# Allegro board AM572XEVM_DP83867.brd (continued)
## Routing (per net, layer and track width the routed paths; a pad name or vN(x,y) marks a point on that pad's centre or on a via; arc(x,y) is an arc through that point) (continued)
GND_EARTH: length 325.7
  TOP w0.381: 109.66,106.27 P5.SHLD1 107.78,106.27 ; 91,106.27 P5.SHLD2 92.88,106.27
  TOP w0.762: P7.S2 P7.S4 ; S2.4 60.45,4.02 v1(60.45,0.89) ; S2.3 51.94,3.97 v1(51.94,0.89) ; v1(25.27,106.68) 25.27,103.26 S1.4 S1.3 33.15,103.26 33.15,106.68
  GND_L2 w0.381: 91,106.27 P5.SHLD2 92.88,106.27 ; 107.78,106.27 P5.SHLD1 109.66,106.27
  INT_L3 w0.381: 107.78,106.27 P5.SHLD1 109.66,106.27 ; 91,106.27 P5.SHLD2 92.88,106.27
  GND_L4 w0.381: 92.88,106.27 P5.SHLD2 91,106.27 ; 109.66,106.27 P5.SHLD1 107.78,106.27
  SIG_L5 w0.381: 109.66,106.27 P5.SHLD1 107.78,106.27 ; 92.88,106.27 P5.SHLD2 91,106.27
  PWR_L6 w0.381: 92.88,106.27 P5.SHLD2 91,106.27 ; 107.78,106.27 P5.SHLD1 109.66,106.27
  PWR_L7 w0.381: 92.88,106.27 P5.SHLD2 91,106.27 ; 107.78,106.27 P5.SHLD1 109.66,106.27
  SIG_L8 w0.381: 107.78,106.27 P5.SHLD1 109.66,106.27 ; 92.88,106.27 P5.SHLD2 91,106.27
  SIG_L8 w0.762: P15.21 P15.19
  GND_L9 w0.381: 107.78,106.27 P5.SHLD1 109.66,106.27 ; 92.88,106.27 P5.SHLD2 91,106.27
  SIG_L10 w0.381: 92.88,106.27 P5.SHLD2 91,106.27 ; 107.78,106.27 P5.SHLD1 109.66,106.27
  SIG_L10 w0.762: P13.10 P13.11 P15.19 110.08,11.42
  GND_L11 w0.381: 107.78,106.27 P5.SHLD1 109.66,106.27 ; 91,106.27 P5.SHLD2 92.88,106.27
  BOTTOM w0.381: D10.1 v1(47.12,0.89) ; C231.2 83.55,1.81 P7.S3 ; R402.2 18.92,96.27 ; R402.2 19.46,95.84 ; R402.2 19.46,96.69 ; v1(113.03,106.68) 112.93,106.58 113.03,106.48 113.03,105.53 C215.2 ; C472.2 16.41,4.32 MH1.1 16.61,3.3 R400.2 ; C472.2 19.71,3.89 ; C472.2 19.71,4.75 ; C472.2 R400.2 ; C474.2 18.92,97.28 ; C474.2 19.46,96.85 ; C474.2 19.46,97.71 ; 92.88,106.27 P5.SHLD2 91,106.27 ; R331.2 100.38,106.63 v1(100.33,106.68) ; 121.24,90.39 R403.2 ; R403.2 121.67,93.8 MH4.1 120.65,93.8 C475.2 ; R403.2 122.09,90.39 ; 120.22,90.39 C475.2 ; C475.2 121.08,90.39 ; R299.2 v1(84.58,106.68) ; R385.2 v1(60.45,0.89) ; 117.06,2.87 R401.2 ; R401.2 C473.2 ; R401.2 117.45,3.73 ; R401.2 120.55,3.3 MH2.1 120.75,4.32 C473.2 ; 19.71,2.87 R400.2 ; R400.2 20.1,2.87 ; C473.2 117.45,3.89 ; C473.2 117.45,4.75 ; D8.1 v1(34.32,0.89) ; C216.2 33.15,106.68 ; 110.08,17.11 110.11,17.14 R300.2 ; 107.78,106.27 P5.SHLD1 109.66,106.27 ; D9.1 v1(29.24,0.89) ; R387.2 v1(63.75,106.68) ; C230.2 v1(51.94,0.89) ; C441.2 v1(51.82,106.68) ; v1(25.78,106.68) 25.27,106.68 v1(25.27,106.68) R332.2 ; 24,106.68 24,106.14 R384.1 24.51,106.14 24.51,106.68 ; R386.2 89.17,1.81 P7.S1 ; C419.1 79.76,11.46 P13.10 ; D11.1 v1(42.04,0.89) ; C415.2 v1(70.36,106.68)
  BOTTOM w0.762: P5.SHLD4 91.96,89 91.96,96.33 91.08,97.21 91.08,102.54 91.94,103.39 P5.SHLD2 ; P11.MTG2 49.94,100.68 P11.MTG4 49.94,106.32 50.29,106.68 v1(51.82,106.68) v1(54.61,106.68) v1(57.15,106.68) v1(59.69,106.68) v1(62.23,106.68) v1(63.75,106.68) 65.28,106.68 65.63,106.32 P11.MTG3 65.63,100.68 P11.MTG1 ; v1(79.76,0.89) 79.76,11.39 P13.10 ; S2.4 S2.3 ; P5.SHLD1 108.72,104.41 109.96,103.17 109.96,99.44 108.72,98.21 P5.SHLD3 ; v1(110.11,0.89) 110.11,11.39 110.08,11.42 110.08,17.11 ; P6.16 P6.17 68.27,106.12 68.83,106.68 v1(70.36,106.68) v1(72.39,106.68) v1(74.93,106.68) v1(77.47,106.68) v1(80.01,106.68) v1(82.55,106.68) v1(84.58,106.68) 85.98,106.68 86.67,105.99 P6.14 P6.15
  vias: v1(13.46,104.01) v1(13.46,101.47) v1(13.46,98.93) v1(13.46,91.31) v1(13.46,88.77) v1(13.46,86.23) v1(13.46,83.69) v1(13.46,81.15) v1(13.46,78.61) v1(13.46,76.07) v1(13.46,73.53) v1(13.46,70.99) v1(13.46,68.45) v1(13.46,65.91) v1(13.46,63.37) v1(13.46,60.83) v1(13.46,58.29) v1(13.46,55.75) v1(13.46,53.21) v1(13.46,50.67) v1(13.46,48.13) v1(13.46,45.59) v1(13.46,43.05) v1(13.46,40.51) v1(13.46,37.97) v1(13.46,35.43) v1(13.46,32.89) v1(13.46,30.35) v1(13.46,27.81) v1(13.46,25.27) v1(13.46,22.73) v1(13.46,20.19) v1(13.46,17.65) v1(13.46,15.11) v1(13.46,12.57) v1(13.46,10.03) v1(13.46,7.49) v1(14.73,105.84) v1(16.51,106.68) v1(19.05,106.68) v1(19.05,0.89) v1(21.59,106.68) v1(21.59,0.89) v1(24.13,106.68) v1(24.13,0.89) v1(26.54,106.68) v1(29.21,106.68) v1(31.75,106.68) v1(31.75,0.89) v1(34.42,106.68) v1(36.83,106.68) v1(39.37,106.68) v1(41.91,106.68) v1(44.45,106.68) v1(44.45,0.89) v1(46.99,106.68) v1(49.53,106.68) v1(54.61,0.89) v1(57.15,0.89) v1(61.59,0.89) v1(63.63,0.89) v1(64.77,0.89) v1(67.31,106.68) v1(67.31,0.89) v1(69.85,0.89) v1(72.39,0.89) v1(75.95,0.89) v1(78.11,0.89) v1(82.55,0.89) v1(87.63,106.68) v1(90.17,106.68) v1(90.17,0.89) v1(92.71,106.68) v1(92.71,0.89) v1(95.25,106.68) v1(95.25,0.89) v1(97.79,106.68) v1(97.79,0.89) v1(100.33,0.89) v1(102.87,106.68) v1(102.87,0.89) v1(105.41,106.68) v1(105.41,0.89) v1(107.95,106.68) v1(107.95,0.89) v1(110.49,106.68) v1(113.03,0.89) v1(115.57,106.68) v1(115.57,0.89) v1(118.11,106.68) v1(118.11,0.89) v1(120.65,106.68) v1(122.66,105.89) v1(123.7,104.01) v1(123.7,101.47) v1(123.7,98.93) v1(123.7,88.52) v1(123.7,85.83) v1(123.7,83.69) v1(123.7,81.15) v1(123.7,78.61) v1(123.7,76.07) v1(123.7,73.53) v1(123.7,70.99) v1(123.7,68.45) v1(123.7,65.91) v1(123.7,63.37) v1(123.7,60.83) v1(123.7,58.29) v1(123.7,55.75) v1(123.7,53.21) v1(123.7,50.67) v1(123.7,48.13) v1(123.7,45.59) v1(123.7,43.05) v1(123.7,40.51) v1(123.7,37.97) v1(123.7,35.43) v1(123.7,32.89) v1(123.7,30.35) v1(123.7,27.81) v1(123.7,25.27) v1(123.7,22.73) v1(123.7,20.19) v1(123.7,17.65) v1(123.7,15.11) v1(123.7,12.57) v1(123.7,10.03) v1(123.7,7.49)
GND_SIGNAL: length 24
  TOP w0.254: v1(55.12,19.81) 55.12,19.78 55.37,19.53 U18.17 56.67,19.53 v1(57.15,19.05) ; v1(57.17,14.5) U18.26 57.17,16.49 v1(57.15,16.51)
  TOP w0.381: C247.2 53.5,23.02 53.98,23.5 v1(55.12,23.5)
  SIG_L8 w0.381: 43.26,4.64 P9.1 ; P9.1 44.58,5.58 ; P9.1 44.58,3.7 ; P9.1 45.9,4.64 ; P8.1 33.1,4.64 ; P8.1 31.78,5.58 ; P8.1 31.78,3.7 ; P8.1 30.45,4.64
  BOTTOM w0.381: R235.2 v1(47.75,13.72) ; FB9.2 56.52,22.35 55.88,21.72 v1(55.88,21.08) ; R234.2 v1(41.15,13.72) ; C248.2 57.75,14.72 57.53,14.5 v1(57.17,14.5) ; v1(52.2,16) 52.58,16.38 C249.2 ; R226.2 v1(35.43,14.35) ; R228.2 v1(28.07,14.35)
  vias: v1(57.15,17.78) v1(58.42,19.05) v1(58.42,17.78) v1(58.42,16.51) v1(59.69,19.05) v1(59.69,17.78) v1(59.69,16.51)
VBUS_DET: length 51.9
  TOP w0.12: v1(68.96,26.92) 68.96,28.7 69.47,29.21 69.98,29.21 70.59,29.82 70.59,30.41 U11.B11
  SIG_L10 w0.094: v1(68.96,26.92) 68.96,26.29 71.63,23.62 74.68,23.62 77.22,21.08 77.22,10.67 78.87,9.02 98.17,9.02 v1(98.81,9.65)
  BOTTOM w0.12: R414.2 97.7,8.03 97.79,8.13 97.79,8.89 97.88,8.98 R413.2 98.3,9.4 98.55,9.65 v1(98.81,9.65)
VCC_SENSE: length 2.8
  TOP w0.12: U5.B3 v2(70.99,76.01)
  BOTTOM w0.12: v2(70.99,76.01) 71.38,75.62 71.95,75.62 72.55,76.22 72.55,76.23 72.7,76.38 R30.2
VCC_SENSE2: length 2
  TOP w0.12: R29.2 73.38,69.21 U5.A11
VDD_1.1: length 19.4
  TOP w0.254: v1(97.92,33.02) 97.84,33.09 U17.31 ; U17.8 92.46,25.39 92.46,24.77 v1(92.33,24.64) ; 88.27,32.59 87.57,32.59 v1(87.53,32.64) ; v1(97.92,31.62) 97.89,31.6 U17.28 ; U17.5 90.96,24.67 v1(90.93,24.64) ; v1(87.5,29.59) 87.51,29.6 88.27,29.6 ; v1(97.92,28.07) 97.89,28.09 U17.21 ; v1(94.87,26.42) 94.96,26.32 U17.13
  BOTTOM w0.254: C486.1 94.93,26.47 v1(94.87,26.42) ; C483.1 v1(87.5,29.59) ; v1(97.92,33.02) 97.66,32.77 C489.1 ; v1(90.93,24.64) C484.1 ; C488.1 v1(97.92,31.62) ; C487.1 v1(97.92,28.07) ; v1(92.33,24.64) 92.46,24.77 C485.1 ; C482.1 v1(87.53,32.64)
  BOTTOM w0.305: R201.1 105.54,37.08 105.02,37.6 U16.9 U16.10 103.71,36.53 v1(103.63,36.45)
  BOTTOM w0.381: v1(97.92,28.07) 97.92,28.7 97.66,28.96 C481.1 ; v1(103,36.45) v1(103.63,36.45)
VDD_1V0: length 20.4
  TOP w0.381: R471.1 87.63,75.16 v1(87.63,75.49) v1(87.05,75.49) ; 111.66,75.34 v1(112.06,75.74) ; 111.66,75.34 v1(111.23,75.77) ; 111.66,75.34 R473.1 ; U5.J8 v2(64.59,71.21)
  SIG_L8 w0.381: 85.86,78.04 TP28.1 ; TP28.1 86.76,78.04 ; TP28.1 86.76,78.93 ; TP28.1 85.86,78.93
  SIG_L10 w0.254: v2(64.59,71.21) 64.58,71.21 63.98,71.81 60.6,71.81 60.07,71.27 60.07,69.32 56.77,66.01 v1(54.41,66.01)
  vias: v1(54.41,66.62) v1(54.41,65.43)
VDD_1V8: length 57.5
  TOP w0.254: U11.P8 v2(72.99,40.01) U11.N8 v2(72.99,39.21) U11.M8 ; U11.W17 v2(64.99,44.81) U11.W18 v2(64.19,44.81) ; U11.H17 v2(64.99,35.21) U11.G18 v2(64.19,34.41) ; U11.M8 v2(72.19,38.41) U11.M9 ; U11.M8 v2(72.99,38.41) ; U11.V21 v2(61.79,44.01) ; v2(61.79,44.01) U11.V22 v2(60.99,44.01) ; v2(61.79,44.01) U11.W21 v2(61.79,44.81) U11.Y21 v2(61.79,45.61) ; U11.N21 v2(62.59,40.01) ; U11.N21 v2(61.79,39.21) ; U11.N21 v2(61.79,40.01) U11.P21 v2(62.59,40.01) ; v2(62.59,40.01) U11.P20 ; U11.J21 v2(61.79,36.01) U11.J22 v2(60.99,36.01) ; U11.R8 v2(72.99,41.61) U11.T8 v2(72.99,42.41) ; U11.Y7 v2(73.79,45.61) U11.AA7 v2(73.79,46.41) ; v2(63.39,46.41) U11.AA19 v2(64.19,46.41) U11.AA18 ; v2(62.99,68.81) U5.L11
  TOP w0.381: v1(56.01,54.74) 56.01,55.12 56.64,55.75 56.64,59.56 L9.2 ; v1(78.99,73.66) 80.39,73.66 81.37,72.68 R302.2
  BOTTOM w0.254: v2(64.19,46.41) 64.5,46.72 C185.1 ; C195.1 72.67,38.72 v2(72.99,38.41) ; C188.1 73.47,45.29 v2(73.79,45.61) ; v2(72.99,42.41) 72.67,42.09 C194.1 ; v2(73.79,46.41) 73.47,46.09 C187.1 ; C186.1 65.3,34.89 v2(64.99,35.21) ; C192.1 64.5,44.49 v2(64.19,44.81) ; C191.1 U11.Y21 v2(61.79,44.81) ; C193.1 U11.V21 v2(61.79,44.01) ; C196.1 61.3,36.32 v2(60.99,36.01)
  BOTTOM w0.381: Q9.3 78.87,74.26 78.87,73.79 v1(78.99,73.66) 80.65,73.66 81.06,74.07 81.06,74.55 ; 81.06,74.55 R425.2 ; 81.06,74.55 81.1,74.51 U43.3 ; v1(56.01,54.74) 56.01,54.99 56.39,55.37 57.95,55.37 C190.1 ; C189.1 v1(58.67,59.94) ; R420.2 50,73.03 U35.3 Q8.3 55.08,73.19 55.88,72.39 55.88,70.61 v1(55.12,69.85)
  vias: v1(58.67,60.58) v1(58.67,59.31)
VDD_2V5: length 15.5
  TOP w0.254: v2(70.99,77.62) 70.59,77.22 U5.B1
  TOP w0.381: R472.1 84.86,74.63 ; 84.86,74.63 v1(84.38,75.11) ; 84.86,74.63 84.79,74.63 v1(84.43,74.27) ; R475.1 109.58,75.34 ; 109.58,75.34 v1(109.14,75.77) ; 109.58,75.34 v1(110.01,75.77)
  PWR_L6 w0.381: TP29.1 86.73,76.77 ; TP29.1 85.84,76.77 ; TP29.1 86.73,75.88 ; TP29.1 85.84,75.88
  SIG_L10 w0.254: v1(71.4,85.45) 71.4,83.21 72.59,82.02 72.59,81 71.98,80.39 71.98,78.61 v2(70.99,77.62)
  vias: v1(70.66,85.46) v1(72.14,85.45)
VDD_3V3: length 220.3
  TOP w0.203: v2(93.82,45.57) U22.M4 ; 93.34,47.62 93.34,47.09 U22.P5 U22.N4 ; v2(92.58,42.06) U22.C6
  TOP w0.254: U11.B23 v2(60.19,30.41) ; U11.AD7 v2(73.79,48.81) U11.AE7 ; U11.H11 v2(70.59,35.21) U11.H10 v2(71.39,35.21) U11.H9 v2(72.19,35.21) U11.H8 ; U6.8 85.84,82.28 86.11,82.02 C30.1 ; v1(96.14,33.53) 95.96,33.71 U17.34 ; v2(65.79,35.21) U11.H16 v2(66.59,35.21) ; U11.R10 v2(71.39,41.61) ; v2(76.19,44.81) U11.W4 v2(75.39,44.81) U11.W5 ; U11.E22 v2(60.99,32.81) U11.D22 v2(60.99,32.01) ; U11.H8 v2(72.99,35.21) ; U11.H8 v2(72.99,36.01) U11.J8 v2(72.99,36.81) U11.K8 ; U17.16 96.46,26.1 v1(96.14,26.42) ; v2(66.59,35.21) U11.G15 v2(66.59,34.41) ; v2(66.59,35.21) U11.H15 ; U11.B6 v2(74.59,30.41) ; v1(89.53,26.42) 89.35,26.6 88.27,26.6 ; U4.5 68.33,18.41 67.85,18.89 R213.1 ; v2(76.19,39.21) U11.N4 v2(75.39,39.21) U11.N5 ; v2(63.39,35.21) U11.H19 v2(64.19,35.21) U11.H18 ; U33.16 v1(76.84,86.36) ; U11.E16 v2(65.79,32.81) U11.D16 v2(65.79,32.01) ; v2(76.19,34.41) U11.G4 v2(75.39,34.41) U11.G5 ; U11.C24 v2(59.39,31.21) ; R15.1 71.41,17.94 71.75,18.29 71.75,18.54 72.1,18.89 R212.1 ; v2(69.39,70.41) U5.D9 ; v2(76.19,42.41) U11.T4 v2(75.39,42.41) U11.T5 ; U11.P10 v2(71.39,40.01) ; U20.8 30.34,37.58 30.23,37.47 30.23,37.08 v1(30.23,37.08) U20.7 ; U33.10 v1(80.64,86.35) ; v2(71.39,32.01) U11.D10 v2(71.39,32.81) U11.E10 ; 88.27,32.1 89.19,32.1 v1(89.28,32) ; v1(66.04,94.74) 65.48,95.3 U21.23 ; U27.10 26.43,19.95 26.25,19.77 25.1,19.77 24.93,19.95 R286.1 ; U11.E5 v2(75.39,32.81) ; U11.E3 v2(76.99,32.81) ; U33.20 v1(76.84,83.31) ; U11.R7 v2(73.79,41.61) ; R474.1 111.02,59.05 v1(110.72,58.75) ; U33.6 v1(80.64,83.31) ; U11.U10 v2(71.39,43.21) ; v2(74.59,47.21) U11.AB6 v2(73.79,47.21) U11.AB7 ; U11.AD5 v2(75.39,48.81) ; U11.AF5 v2(75.39,49.61)
  TOP w0.381: R212.1 72.26,20.32 v1(71.75,20.83) ; v1(66.68,20.83) 67.44,20.07 R213.1 C15.1 ; v1(87,82.17) R33.1 C30.1 ; v1(122.3,67.56) 121.12,67.56 R189.2 ; L12.1 v1(60.33,22.61) ; R288.2 v1(24.38,21.34) ; v1(93.34,48.13) 93.34,47.62 ; v1(73.39,26.15) 73.39,25.62 73.77,25.24 R59.1 ; v1(89.66,36.32) 89.7,36.29 R243.1 ; v1(28.32,57.15) 27.69,56.52 R313.2 R310.1 26.8,56.52 26.16,57.15 v1(25.91,57.15) ; R437.1 108.37,55.39 108.37,55.39 108.4,55.39 108.67,55.66 U44.5 108.67,57.43 C501.1 v1(108.69,58.11) ; R309.1 v1(24.89,51.94) ; R392.1 R391.1 v1(83.7,80.55) ; v1(111.3,58.75) 111.05,58.75 ; 111.05,58.75 v1(110.72,58.75) ; 111.05,58.75 v1(111.05,58.22) ; v1(24.38,20.45) R286.1 ; R204.2 v1(95,37.08) ; R62.1 v1(74.3,20.83) ; R470.1 v1(96.95,60.45) ; R399.1 R398.1 82.64,85.96 82.26,86.34 v1(81.9,86.34) ; v1(69.82,4.33) 70.12,4.63 C272.2 70.1,5.22 70.1,5.59 70.46,5.94 C271.1 v1(70.46,7.19) ; v1(76.45,71.63) 76.2,71.88 C50.1 ; v1(122.3,62.48) R197.2 R196.2 ; R476.1 83.21,62.41 83.39,62.59 U51.5 83.39,64.4 83.4,64.41 C585.1 v1(83.4,65.14)
  SIG_L5 w0.381: v1(104.39,9.65) 104.78,9.27 117.68,9.27 P18.A3
  PWR_L7 w0.381: J6.3 116.79,91.51 ; J6.3 116.79,92.94 ; J6.3 115.36,92.94 ; J6.3 115.36,91.51 ; 20.86,11.62 P17.A3 ; P17.A3 22.23,12.79 ; P17.A3 22.23,10.44 ; P17.A3 23.61,11.62 ; 22.23,52.35 P19.A3 ; P19.A3 20.86,53.53 ; P19.A3 23.61,53.53 ; P19.A3 22.23,54.7 ; P16.A3 121.4,53.53 ; P16.A3 118.65,53.53 ; P16.A3 120.03,52.35 ; P16.A3 120.03,54.7 ; 120.03,10.44 P18.A3 ; P18.A3 120.03,12.79 ; P18.A3 121.4,11.62 ; P18.A3 118.65,11.62 ; 110.06,96.37 J3.1 ; J3.1 111.94,98.25 ; J3.1 111.94,96.37 ; J3.1 110.06,98.25 ; 110.06,95.71 J4.1 ; J4.1 111.94,93.83 ; J4.1 111.94,95.71 ; J4.1 110.06,93.83
  BOTTOM w0.254: v2(64.19,35.21) 64.59,35.6 C129.1 ; C127.1 70.19,35.6 v2(70.59,35.21) ; C491.1 90.37,26.87 89.92,26.42 v1(89.53,26.42) ; C492.1 v1(96.14,33.53) ; C136.1 U11.D16 v2(65.79,32.81) ; C121.1 75.79,39.6 v2(75.39,39.21) ; v2(74.59,47.21) U11.AB6 C118.1 ; C116.1 74.99,50.01 v2(75.39,49.61) ; C139.1 66.9,34.72 v2(66.59,34.41) ; C137.1 61.39,32.4 v2(60.99,32.01) ; v2(75.39,44.81) U11.W4 C119.1 ; v2(75.39,42.41) U11.T4 C120.1 ; C132.1 U11.H8 v2(72.99,36.01) ; C123.1 71.07,41.29 v2(71.39,41.61) ; v2(75.39,34.41) 74.99,34.8 C115.1 ; v2(66.59,35.21) 66.9,35.52 C128.1 ; v2(73.79,41.61) U11.R7 C124.1 ; C133.1 74.28,30.72 v2(74.59,30.41) ; v1(76.84,86.36) 76.84,86.35 C471.1 ; C126.1 72.67,37.12 v2(72.99,36.81) ; C490.1 v1(89.28,32) ; v2(71.39,40.01) U11.P10 C125.1 ; v2(60.19,30.41) 59.88,30.72 C138.1 ; C135.1 U11.D10 v2(71.39,32.81) ; C493.1 96.39,27.3 96.14,27.05 v1(96.14,26.42) ; v2(76.99,32.81) 77.39,33.2 C114.1 ; C134.1 74.99,33.2 v2(75.39,32.81) ; C117.1 73.47,48.49 v2(73.79,48.81) ; C470.1 80.65,83.32 v1(80.64,83.31)
  BOTTOM w0.305: U16.5 100.06,39.1 v1(99.82,38.86) 100.08,38.6 U16.4 ; U16.2 100.08,37.6 v1(99.82,37.34) 100.06,37.1 U16.1
  BOTTOM w0.381: v1(89.28,32) 89.79,32 90.04,31.75 C494.1 ; v1(80.39,50.42) 80.01,50.04 80.01,49.66 C130.1 ; v2(61.39,77.61) 61.59,77.82 R18.2 R19.2 ; v1(69.82,4.33) 70,4.14 70,3.15 69.82,2.96 P12.4 ; v1(80.39,40.75) 80.2,40.94 80.2,41.34 C131.1 ; C263.2 30.46,37.3 v1(30.23,37.08) ; 52.54,77.34 R418.1 ; 52.54,77.34 R37.2 ; 52.54,77.34 53.09,77.34 v1(53.21,77.47) v1(54.05,77.47) 54.18,77.34 54.77,77.34 ; R247.1 R245.1 R246.1 ; R246.1 R248.1 v1(66.04,94.74) ; R246.1 65.02,95 v1(65.28,94.74) ; R321.1 v1(56.77,26.92) ; v1(28.32,57.15) 27.48,57.15 L23.1 26.88,57.15 v1(25.91,57.15) ; v1(24.38,20.45) 24.64,20.19 C389.1 ; C122.1 79.88,33.66 v1(79.5,33.27) ; 54.77,77.34 C81.1 54.8,77.88 U8.8 ; 54.77,77.34 R419.1 54.77,75.62 Q8.2 ; R46.1 v1(60.33,26.92) ; v1(59.44,26.04) 59.18,25.78 C113.1 59.66,25.24 R38.2 ; 67.94,24.3 v1(67.94,22.35) ; L22.1 30.72,56.88 v1(30.99,57.15) ; R45.1 v1(71.37,79.88) ; R415.1 100.04,8.98 100.22,9.16 U42.5 100.9,9.59 101.23,9.92 104.12,9.92 v1(104.39,9.65) R408.1 ; C269.1 92.62,48.8 C268.1 v1(93.34,48.13) ; R294.1 v1(98.68,41.27) ; R32.1 v1(74.17,67.31) ; R17.1 v1(63.63,79.88) ; R48.1 v1(56.64,54.74) ; R237.1 v1(59.31,102.87) ; R16.1 v1(59.05,77.47) ; R249.2 v1(94.61,50.42) v1(95.25,50.42) 95.25,49.91 95.09,49.75 R249.2
  vias: v1(43.93,67.31) v1(44.7,67.31) v1(96.93,59.59) v1(97.64,59.59)
VDD_3V3_ON: length 30.9
  TOP w0.12: U2.3 42.93,71 v1(43.18,71.25) ; v2(67.79,71.21) U5.F8
  BOTTOM w0.12: R10.2 42.71,69.97 42.82,69.85 50.29,69.85 51.31,68.83 55.45,68.83 56.21,69.6 59.05,69.6 59.31,69.85 60.96,69.85 61.11,70 64.73,70 65,70.27 65,70.57 65.24,70.82 67.4,70.82 v2(67.79,71.21) ; R10.2 42.71,70.77 v1(43.18,71.25) ; R10.2 41.82,70.36 R434.1
VDD_3V3_SP: length 99.7
  TOP w0.381: v1(59.72,10.77) U12.6 60.83,9.84 60.99,9.69 C104.1 ; R52.1 v1(52.7,11.3)
  INT_L3 w0.381: v1(52.7,11.3) 53.72,10.29 59.23,10.29 v1(59.72,10.77) 60.55,9.93 60.55,9.09 61.98,7.67 69.85,7.67 71.35,9.17 73.69,9.17 74.4,9.88 75.56,9.88 76.09,10.4 76.09,11.57 78.23,13.72 78.23,19.18 80.26,21.21 80.26,29.59 80.9,30.23 81.79,30.23 82.79,31.23 82.79,50.81 80.01,53.59 80.01,57.66 80.52,58.17 80.52,60.96 v1(80.01,61.47)
  BOTTOM w0.381: R405.1 81.92,69.71 ; R405.1 82.34,69.31 ; R405.1 81.49,69.31 ; C94.1 77,59.74 ; C94.1 77,58.88 ; C94.1 76.59,59.31 ; R44.1 80.9,64.26 ; R44.1 80.87,64.69 ; R44.1 80.29,63.83 ; R44.1 R42.1 ; 80.9,65.28 R42.1 ; R42.1 80.87,64.85 ; R42.1 80.29,64.85 ; 77.47,60.08 U9.5 77.47,61.2 ; U10.5 79.36,59.7 79.54,59.53 C97.1 ; U10.5 79.74,60.64 ; U10.5 78.98,60.64 ; U10.5 79.36,61.2 ; C97.1 79.15,58.88 ; C97.1 79.54,58.88 ; 77.94,65.2 R41.1 77.94,64.34 ; 81.06,69.8 U34.8 80.76,68.99
VDD_CDC: length 7.7
  TOP w0.254: v1(30.99,54.1) 30.96,53.95 U7.1 ; U7.4 v1(29.46,54.1)
  TOP w0.381: v1(30.99,54.1) C433.1
  BOTTOM w0.381: C430.1 29.46,53.89 v1(29.46,54.1) 29.46,54.49 L22.3 30.59,54.88 30.99,54.48 v1(30.99,54.1) 31.62,54.1 32,54.48 C431.1
VDD_CORE: length 40.7
  TOP w0.254: U11.U13 v2(68.99,42.41) U11.T13 ; v2(71.39,39.21) U11.N10 v2(70.59,40.01) U11.P11 v2(69.79,40.01) U11.P12 v2(68.99,40.01) ; U5.K6 v2(63.79,73.61) ; v2(72.19,43.21) U11.V8 ; v2(72.19,43.21) U11.U9 ; v2(72.19,43.21) U11.U8 v2(72.99,43.21) U11.V8 ; U11.V8 v2(72.99,44.01) ; U11.P13 v2(68.99,40.01) ; v2(68.99,40.01) U11.N13 v2(68.99,39.21) ; U11.H14 v2(68.19,35.21) U11.H13 v2(68.99,35.21) ; v2(65.79,44.01) U11.V16 v2(65.79,43.21) U11.U16 v2(65.79,42.41) U11.T16 v2(65.79,41.61) U11.R16 ; U11.R11 v2(70.59,41.61) ; v2(64.19,36.01) U11.J18 v2(64.99,36.01) U11.J17 ; U11.R19 v2(63.39,41.61) U11.T19 v2(63.39,42.41) ; v2(73.79,37.61) U11.L7 v2(72.99,37.61) U11.L8
  TOP w1.016: P3.3 R36.2
  SIG_L8 w0.381: 83.83,75.83 TP18.1 ; TP18.1 84.72,75.83 ; TP18.1 83.83,76.72 ; TP18.1 84.72,76.72 ; P3.3 57.87,76.92 ; P3.3 56.43,75.48 ; P3.3 56.43,76.92 ; P3.3 57.87,75.48
  BOTTOM w0.254: v2(72.19,43.21) U11.U9 C67.2 ; C62.2 U11.T19 ; U11.T19 v2(63.39,42.41) ; U11.T19 v2(63.39,41.61) ; v2(65.79,43.21) 65.47,42.89 C56.2 65.47,42.72 v2(65.79,42.41) 65.47,42.09 C66.2 65.47,41.92 v2(65.79,41.61) ; v2(72.99,44.01) 73.3,43.69 C55.2 73.3,43.52 v2(72.99,43.21) ; v2(68.99,35.21) 68.67,35.52 C58.2 ; v2(64.99,36.01) 64.67,36.32 C71.2 ; C65.1 72.67,37.92 v2(72.99,37.61) ; v2(68.99,40.01) 68.59,40.4 C72.2 ; v2(70.59,41.61) 70.27,41.29 C60.2
  BOTTOM w0.381: C54.1 79.88,43.81 v1(79.5,43.43)
VDD_DDR: length 210.1
  TOP w0.254: v2(45.78,41.61) U24.D9 ; v2(61.79,46.41) U11.AB21 v2(61.79,47.21) ; v2(61.79,46.41) U11.AB22 v2(61.79,47.21) ; v2(61.79,46.41) U11.AA22 ; v2(61.79,46.41) U11.AA21 ; C376.1 36.27,19.11 v2(36.18,19.2) U25.R9 ; v2(48.18,31.2) U26.A8 ; v2(42.58,30.4) U26.H9 ; v2(60.99,35.21) U11.G22 v2(60.99,34.41) U11.G23 ; v2(60.99,35.21) U11.H22 v2(61.79,35.21) U11.H21 v2(62.59,35.21) U11.H20 ; v2(60.99,35.21) U11.G23 ; C293.1 37.87,52.72 v2(37.78,52.81) U23.N9 ; v2(62.59,38.41) U11.L20 v2(62.59,37.61) U11.L21 ; v2(62.59,38.41) U11.L21 ; v2(62.59,38.41) U11.M20 ; v2(62.59,38.41) U11.M21 v2(61.79,38.41) U11.L21 ; C348.1 37.87,30.32 v2(37.78,30.4) U26.N9 ; C292.1 36.27,52.72 v2(36.18,52.81) U23.R9 ; v2(44.18,48.81) U24.F1 ; v2(46.58,30.4) U26.C9 ; v2(40.18,31.2) U26.K8 ; U11.AG28 v2(56.18,51.21) ; v2(43.38,43.21) U24.G7 ; C319.1 37.87,41.52 v2(37.78,41.61) U24.N9 ; v2(48.18,60.01) U23.A1 ; v2(61.79,47.21) U11.AC22 v2(60.99,48.01) ; v2(42.58,52.81) U23.H9 ; v2(42.58,48.01) U24.H2 ; U11.T25 v2(59.39,42.41) U11.T24 ; v2(42.58,41.61) U24.H9 ; v2(47.38,36.8) U26.B2 ; U27.2 30.73,20.45 ; C306.1 36.27,48.89 v2(36.18,48.81) U24.R1 ; C307.1 37.87,48.89 v2(37.78,48.81) U24.N1 ; U11.J27 v2(56.99,36.01) ; v2(44.98,19.2) U25.E9 ; C335.1 36.27,37.69 v2(36.18,37.6) U26.R1 ; U11.AB24 v2(59.39,47.21) U11.AB25 ; C392.1 31.28,19.38 31.6,19.05 31.83,19.05 32.22,18.65 R285.1 ; C284.1 37.87,60.1 v2(37.78,60.01) U23.N1 ; U11.L21 v2(61.79,37.61) ; U11.W16 v2(65.79,44.81) ; v2(44.18,26.4) U25.F1 ; C318.2 36.27,41.52 v2(36.18,41.61) U24.R9 ; v2(43.38,54.41) U23.G7 ; v2(40.18,48.01) U24.K2 ; C364.1 37.87,26.49 v2(37.78,26.4) U25.N1 ; v2(48.18,42.41) U24.A8 ; v2(48.18,20) U25.A8 ; v2(40.18,59.21) U23.K2 ; v2(43.38,20.8) U25.G7 ; v2(46.58,48.81) U24.C1 ; v2(42.58,19.2) U25.H9 ; v2(40.18,42.41) U24.K8 ; v2(46.58,37.6) U26.C1 ; v2(42.58,59.21) U23.H2 ; U11.G23 v2(60.19,34.41) ; C283.1 36.27,60.1 v2(36.18,60.01) U23.R1 ; U26.N1 v2(37.78,37.6) 37.87,37.69 C336.1 ; C363.1 36.27,26.49 v2(36.18,26.4) U25.R1 ; U11.AH27 v2(56.99,52.01) ; v2(47.38,48.01) U24.B2 ; v2(45.78,59.21) U23.D2 ; C377.1 37.87,19.11 v2(37.78,19.2) U25.N9 ; v2(45.78,36.8) U26.D2 ; v2(45.78,52.81) U23.D9 ; v2(46.58,60.01) U23.C1 ; v2(40.18,53.61) U23.K8 ; v2(46.58,26.4) U25.C1 ; v2(47.38,59.21) U23.B2 ; v2(43.38,32) U26.G7 ; U11.W27 v2(56.99,44.81) ; v2(63.79,67.21) U5.K13 ; v2(47.38,25.6) U25.B2 ; v2(40.18,36.8) U26.K2 ; U11.AD26 v2(57.79,48.81) ; v2(45.78,25.6) U25.D2 ; v2(46.58,41.61) U24.C9 ; v2(46.58,19.2) U25.C9 ; U11.AG20 v2(62.59,50.41) ; v2(45.78,30.4) U26.D9 ; v2(44.18,37.6) U26.F1 ; v2(44.98,30.4) U26.E9 ; v2(42.58,36.8) U26.H2 ; v2(46.58,52.81) U23.C9 ; v2(44.98,52.81) U23.E9 ; v2(48.18,37.6) U26.A1 ; v2(45.78,48.01) U24.D2 ; v2(48.18,48.81) U24.A1 ; v2(40.18,25.6) U25.K2 ; v2(48.18,53.61) U23.A8 ; U11.E24 v2(59.39,32.81) ; v2(42.58,25.6) U25.H2 ; U26.R9 v2(36.18,30.4) 36.27,30.32 C347.1 ; v2(44.98,41.61) U24.E9 ; v2(45.78,19.2) U25.D9 ; v2(40.18,20) U25.K8 ; v2(44.18,60.01) U23.F1 ; v2(48.18,26.4) U25.A1
  TOP w0.381: C392.1 C391.1 31.27,20.45 30.73,20.45 ; v1(32.89,18.54) R285.1 ; C295.1 47.75,60.44 v2(48.18,60.01)
  INT_L3 w0.381: v1(63.5,59.94) v1(63.5,60.58) 62.36,61.72 62.36,65.34 63.79,66.77 v2(63.79,67.21)
  PWR_L6 w0.381: 50.61,45.53 TP16.1 ; TP16.1 50.61,46.42 ; TP16.1 51.5,46.42 ; TP16.1 51.5,45.53
  PWR_L7 w0.381: TP16.1 51.5,45.53 ; TP16.1 50.61,46.42 ; TP16.1 50.61,45.53 ; TP16.1 51.5,46.42
  BOTTOM w0.254: C287.1 44.58,59.61 v2(44.18,60.01) ; C355.1 43.78,31.6 v2(43.38,32) ; C171.1 57.38,51.61 v2(56.99,52.01) ; v2(45.78,59.21) 45.47,58.89 C288.1 ; C338.1 42.9,36.49 v2(42.58,36.8) 42.27,36.49 C281.2 ; v2(46.58,48.81) U24.C1 C315.1 ; v2(45.78,25.6) 45.47,25.29 C368.1 ; C168.1 57.3,36.32 v2(56.99,36.01) ; v2(45.78,36.8) 45.47,36.49 C340.1 ; v2(46.58,52.81) U23.C9 C304.1 ; C169.1 61.3,34.72 v2(60.99,34.41) ; v2(47.38,48.01) 47.07,47.69 C316.1 ; v2(60.99,35.21) 61.3,35.52 C175.1 ; v2(34.58,20.8) C331.2 C330.2 ; v2(34.58,48.81) C342.2 C343.2 ; v2(44.98,41.61) U24.E9 C323.1 ; C373.1 U25.C1 v2(46.58,26.4) ; C357.1 U26.D9 v2(45.78,30.4) ; v2(46.58,41.61) U24.C9 C325.1 ; C162.1 U11.AB22 v2(61.79,47.21) U11.AB21 C172.1 ; v2(48.18,31.2) 47.87,31.52 C360.1 ; C382.1 43.78,20.4 v2(43.38,20.8) 42.79,21.4 C334.1 ; C277.2 42.27,58.89 v2(42.58,59.21) 42.9,58.89 C286.1 ; v2(40.18,59.21) 40.5,58.89 C285.1 ; C157.1 56.5,50.89 v2(56.18,51.21) ; v2(46.58,60.01) U23.C1 C289.1 ; C365.1 40.5,25.29 v2(40.18,25.6) ; C359.1 U26.C9 v2(46.58,30.4) ; v2(47.38,25.6) 47.07,25.29 C374.1 ; C388.1 42.79,43.8 v2(43.38,43.21) 43.78,42.81 C322.1 ; C324.1 U24.D9 v2(45.78,41.61) ; v2(48.18,53.61) 47.87,53.92 C305.1 ; v2(61.79,37.61) 62.1,37.29 C181.1 ; v2(59.39,32.81) 59.07,33.12 C178.1 ; C183.1 62.9,37.92 v2(62.59,37.61) ; C159.1 U11.AD26 v2(57.79,48.81) ; C160.1 57.3,44.49 v2(56.99,44.81) ; v2(42.58,25.6) 42.9,25.29 C366.1 ; v2(44.98,19.2) U25.E9 C383.1 ; v2(46.58,37.6) U26.C1 C344.1 ; C161.1 59.7,46.89 v2(59.39,47.21) ; v2(40.18,36.8) 40.5,36.49 C337.1 ; C163.1 55.08,44.04 54.74,43.69 54.48,43.69 54.14,43.34 R273.1 ; C356.1 U26.E9 v2(44.98,30.4) ; v2(48.18,26.4) U25.A1 C375.1 ; v2(61.79,38.41) 62.19,38.8 C167.1 ; C328.2 C329.2 42.89,23.92 43.18,23.62 v1(43.18,23.37) ; C332.2 v2(34.58,19.2) ; v2(34.58,24.8) C314.2 C313.2 ; v2(60.99,48.01) 61.3,47.69 C170.1 ; v2(65.79,44.81) 66.1,44.49 C182.1 ; v2(44.18,26.4) 44.58,26 C367.1 ; v2(34.58,47.21) C358.2 C353.2 ; C333.2 41.7,18.31 v2(42.58,19.2) 42.98,19.6 C381.1 ; C173.1 U11.AA21 v2(61.79,46.41) U11.AA22 C164.1 ; C291.1 U23.A1 v2(48.18,60.01) ; v2(45.78,48.01) 45.47,47.69 C311.1 ; v2(34.58,26.4) C296.2 C297.2 ; v2(44.18,37.6) 44.58,37.2 C339.1 ; C301.1 43.78,54.01 v2(43.38,54.41) ; v2(62.59,38.41) 62.99,38.8 C166.1 ; C380.2 41.7,40.72 v2(42.58,41.61) 42.98,42.01 C321.1 ; v2(48.18,48.81) U24.A1 C317.2 ; C302.1 U23.E9 v2(44.98,52.81) ; C379.2 v2(34.58,41.61) ; v2(48.18,20) 47.87,20.31 C386.1 ; C300.1 42.98,53.21 v2(42.58,52.81) ; v2(45.78,19.2) U25.D9 C384.1 ; C158.1 62.99,50.8 v2(62.59,50.41) 62.19,50.81 C184.1 ; C371.2 C372.2 v2(34.58,43.21) ; C346.1 U26.A1 v2(48.18,37.6) ; C320.1 40.5,42.72 v2(40.18,42.41) ; v2(48.18,42.41) 47.87,42.72 C326.1 ; C165.1 59.7,42.09 v2(59.39,42.41) 59.7,42.72 C174.1 ; v2(47.38,36.8) 47.07,36.49 C345.1 ; C310.1 44.58,48.41 v2(44.18,48.81) 43.3,49.69 C352.2 C351.2 ; C308.1 40.5,47.69 v2(40.18,48.01) ; v2(46.58,19.2) U25.C9 C385.1 ; v2(61.79,35.21) 62.19,34.8 C176.1 ; C290.2 47.07,58.89 v2(47.38,59.21) ; C177.1 62.99,35.6 v2(62.59,35.21) ; v2(40.18,20) 40.5,20.31 C378.1 ; C309.1 42.9,47.69 v2(42.58,48.01) 42.27,47.69 C278.2 41.78,47.29 C362.2 C370.2 ; v2(40.18,31.2) 40.5,31.52 C349.1 ; v1(42.55,27.94) 42.55,27.56 42.28,27.29 C299.2 C298.2 ; v2(42.58,30.4) 42.98,30.8 C354.1 ; C303.1 U23.D9 v2(45.78,52.81) ; v2(40.18,53.61) 40.5,53.92 C294.1
  BOTTOM w0.381: v1(32.89,18.54) 31.75,18.54 C394.1 C393.1 32.26,20.19 v1(32.89,19.56) ; C361.1 46.22,18.76 v2(45.78,19.2) ; C327.1 47.75,49.24 v2(48.18,48.81) ; v2(45.78,52.81) 46.22,52.37 C312.1 ; v1(55.25,44.83) v1(54.48,44.83) 54.48,45.59 C156.1 55.25,45.59 v1(55.25,44.83) ; v1(55.25,44.83) 55.08,44.67 C163.1 ; C179.1 55.08,31.78 v1(55.25,31.62) ; C350.1 47.75,26.84 v2(48.18,26.4) ; v1(55.25,31.62) 55.25,30.86 C180.1 54.48,30.86 v1(54.48,31.62) v1(55.25,31.62) ; v2(45.78,41.61) 46.22,41.17 C369.1 ; C341.1 47.75,38.04 v2(48.18,37.6) ; C387.1 46.22,29.97 v2(45.78,30.4)
  vias: v1(63.5,59.31)
VDD_DSP: length 61.2
  TOP w0.254: U11.K11 v2(69.79,36.81) U11.K12 ; U11.K11 v2(69.79,37.61) ; U11.K11 v2(70.59,37.61) ; U11.K11 v2(70.59,36.81) U11.K10 ; U11.V14 v2(68.19,44.01) U11.W13 v2(68.99,44.81) ; U11.K12 v2(69.79,37.61) ; U11.K12 v2(68.99,36.81) ; v2(69.79,37.61) U11.L12 ; v2(69.79,37.61) U11.L11 ; U11.K10 v2(71.39,37.61) U11.L10 ; U11.K10 v2(70.59,37.61) ; U11.K10 v2(71.39,36.81) ; U11.V19 v2(63.39,43.21) U11.U19 v2(64.19,43.21) ; U11.V19 v2(64.19,44.01) U11.V18 v2(64.19,43.21) ; U11.V19 v2(64.19,43.21) ; U11.V19 v2(63.39,44.01) ; U11.W10 v2(71.39,44.81) ; U11.W10 v2(71.39,44.01) U11.V10 ; U11.W10 v2(70.59,44.81) U11.W11 v2(70.59,44.01) ; U11.W10 v2(70.59,44.01) ; v2(64.19,43.21) U11.U18 ; v2(69.79,43.21) U11.U11 v2(70.59,43.21) ; v2(69.79,43.21) U11.V11 ; v2(69.79,43.21) U11.U12 ; v2(69.79,38.41) U11.L11 ; v2(69.79,38.41) U11.M11 v2(70.59,38.41) ; v2(69.79,38.41) U11.M12 v2(68.99,38.41) ; v2(69.79,38.41) U11.L12 ; U11.L11 v2(70.59,38.41) ; U11.L11 v2(70.59,37.61) ; v2(70.59,38.41) U11.M10 v2(71.39,38.41) U11.L10 ; v2(70.59,38.41) U11.L10 ; v2(70.59,37.61) U11.L10 ; v2(70.59,44.01) U11.V10 ; v2(70.59,44.01) U11.V11 ; U11.V11 v2(70.59,43.21) ; v2(70.59,43.21) U11.V10 ; U11.L12 v2(68.99,38.41) ; v2(68.99,38.41) U11.M13 ; U11.K13 v2(68.99,36.81) ; v2(68.99,36.81) U11.J13 v2(68.99,36.01) ; U5.K2 v2(63.79,76.81)
  TOP w1.016: P3.2 R35.2
  PWR_L6 w0.381: 83.88,78.93 TP17.1 ; TP17.1 84.77,78.93 ; TP17.1 84.77,78.04 ; TP17.1 83.88,78.04
  SIG_L8 w0.381: P3.2 57.87,79.46 ; P3.2 56.43,79.46 ; P3.2 57.87,78.02 ; P3.2 56.43,78.02 ; 83.88,78.93 TP17.1 ; TP17.1 84.77,78.93 ; TP17.1 83.88,78.04 ; TP17.1 84.77,78.04
  BOTTOM w0.254: C59.1 70.19,38 v2(70.59,37.61) ; C52.2 69.39,38 v2(69.79,37.61) ; v2(64.19,43.21) 63.87,43.52 C68.1 ; C51.1 70.99,38 v2(71.39,37.61) ; v2(68.99,38.41) 69.3,38.72 C57.1 ; v2(63.39,43.21) 63.7,42.89 C69.1 ; C74.1 70.27,44.49 v2(70.59,44.81) ; v2(70.59,43.21) 70.27,43.52 C78.2 ; C61.1 68.67,36.32 v2(68.99,36.01) ; C76.1 U11.V14 v2(68.19,44.01) ; C73.1 71.07,44.49 v2(71.39,44.81) ; v2(68.99,44.81) U11.W13 C79.1 ; v2(69.79,43.21) U11.U12 C75.1
  BOTTOM w0.381: v1(79.5,35.56) C80.1 C70.1 C64.1 ; C64.1 v1(79.5,37.59) ; C64.1 C63.1 80.17,39.59 C53.1 79.63,40.13 79.63,40.64 v1(79.5,40.77)
  vias: v1(83.31,79.25) v1(83.31,78.74) v1(83.31,78.23) v1(83.31,77.72)
VDD_MPU: length 51.9
  TOP w0.254: v2(64.99,38.41) U11.M18 ; v2(64.99,38.41) U11.L18 ; v2(64.99,38.41) U11.M17 ; v2(64.99,38.41) U11.L17 ; U11.M18 v2(64.99,39.21) ; U11.M18 v2(64.19,39.21) U11.N18 ; U11.M18 v2(64.19,38.41) ; U11.K18 v2(64.19,37.61) ; U11.K18 v2(64.99,37.61) ; U11.K18 v2(64.19,36.81) ; U11.K18 v2(64.99,36.81) U11.K17 ; v2(64.19,37.61) U11.L19 ; v2(64.19,37.61) U11.L18 ; U11.K17 v2(65.79,37.61) ; U11.K17 v2(64.99,37.61) ; v2(65.79,37.61) U11.L16 ; v2(65.79,37.61) U11.L17 ; v2(65.79,38.41) U11.M16 v2(66.59,38.41) ; v2(65.79,38.41) U11.L17 ; v2(65.79,38.41) U11.M17 ; v2(65.79,38.41) U11.L16 ; v2(64.99,37.61) U11.L18 ; v2(64.99,37.61) U11.L17 ; U11.L16 v2(66.59,38.41) ; U11.L18 v2(64.19,38.41) ; v2(64.99,40.01) U11.N17 v2(64.99,39.21) ; v2(64.99,40.01) U11.P17 ; v2(64.99,40.01) U11.P18 v2(64.19,40.01) U11.N18 ; v2(64.99,40.01) U11.N18 ; U11.L19 v2(64.19,38.41) ; U11.L19 v2(63.39,37.61) ; v2(64.99,39.21) U11.N18 ; v2(64.99,39.21) U11.M17 ; U11.L15 v2(66.59,38.41) ; v2(66.59,38.41) U11.M15 ; U5.B13 v2(70.99,67.21) ; U11.R18 v2(64.19,41.61)
  TOP w0.381: U12.5 60.45,8.89 60.99,8.35 R54.2 v1(62.45,8.35)
  TOP w1.016: P3.5 TP13.1 R34.2
  PWR_L6 w0.381: 56.43,70.4 P3.5 ; P3.5 56.43,71.84 ; P3.5 57.87,70.4 ; P3.5 57.87,71.84 ; 55.56,70.67 TP13.1 55.56,71.57
  SIG_L8 w0.381: P3.5 57.87,70.4 ; P3.5 57.87,71.84 ; P3.5 56.43,71.84 ; P3.5 56.43,70.4 ; 54.67,71.57 TP13.1 ; TP13.1 55.56,71.57 ; TP13.1 55.56,70.67 ; TP13.1 54.67,70.67
  BOTTOM w0.254: C88.2 65.39,39.6 v2(64.99,39.21) ; C87.1 U11.P17 v2(64.99,40.01) ; v2(65.79,37.61) 65.47,37.92 C90.1 ; v2(64.19,39.21) 64.5,39.52 C77.1 ; C85.1 66.99,38 v2(66.59,38.41) 66.99,38.8 C86.1 ; v2(65.79,38.41) 65.47,38.72 C91.1 ; C84.1 64.5,40.32 v2(64.19,40.01) ; v2(64.19,38.41) 64.5,38.72 C82.1 ; C83.1 64.5,37.92 v2(64.19,37.61) ; v2(64.99,37.61) 64.67,37.29 C89.2 64.67,37.12 v2(64.99,36.81)
  BOTTOM w0.381: v1(74.17,66.55) 73.41,66.55 C93.1 ; v2(70.99,67.21) 70.99,66.52 C92.2
VDD_RTC: length 4.9
  TOP w0.254: U11.AB15 v2(66.59,47.21)
  TOP w0.381: v1(74.17,74.42) 71.8,74.42 U5.A5
  BOTTOM w0.254: v2(66.59,47.21) 66.64,47.15 C108.1
  BOTTOM w0.381: C28.2 v1(74.17,74.42)
VDD_SD: length 15.2
  TOP w0.254: v2(70.19,72.81) U5.C6 ; U11.W8 v2(72.99,44.81) U11.Y8 v2(72.99,45.61) ; D23.1 63.89,11.59 63.7,11.4 63.7,10.56 R272.1 63.72,10.2 v1(63.32,9.8) ; v1(74.12,10.67) 74.08,10.63 D22.1 ; D21.1 69.63,15.2 v1(69.67,15.24) ; D20.1 65.19,10.55 v1(65.38,10.74)
  TOP w0.381: v1(74.12,10.67) R264.1 ; R261.1 v1(66.5,10.67) ; R262.1 v1(67.77,10.67) ; R260.1 65.23,10.9 v1(65.38,10.74) ; R263.1 v1(72.85,10.67) ; R265.1 v1(75.39,10.67)
  INT_L3 w0.381: v1(69.67,15.24) v1(70.94,15.24)
  BOTTOM w0.254: v2(72.99,44.81) 72.59,45.2 C140.1
  BOTTOM w0.381: v2(70.19,72.81) 70.75,73.37 71.28,73.37 71.51,73.14 72.28,73.14 C21.2
VDD_SHV5: length 19.1
  TOP w0.254: U11.V12 v2(68.99,43.21) ; v2(70.99,72.81) U5.B6
  SIG_L10 w0.381: v2(70.99,72.81) 71.08,72.9 76.84,72.9 77.22,72.52 77.22,71.25 76.96,70.99 v1(76.45,70.99)
  BOTTOM w0.254: C105.1 67.83,42.93 68.71,42.93 v2(68.99,43.21)
  BOTTOM w0.381: C22.2 72.14,72.39 72,72.53 71.27,72.53 v2(70.99,72.81) ; R423.1 79.12,70.99 78.49,70.36 77.47,70.36 77.25,70.58 R424.1 ; v1(76.45,70.99) R424.1 ; R424.1 77.25,71.95 Q9.2
VDDA_1V8_PHYA: length 4.1
  TOP w0.254: v2(63.79,68.81) U5.K11 ; v2(69.79,47.21) U11.AB12 v2(68.99,46.41) U11.AA13
  BOTTOM w0.254: v2(68.99,46.41) 69.07,46.41 C243.1 69.47,46.89 v2(69.79,47.21)
  BOTTOM w0.381: C245.1 v1(79.5,48.26)
  vias: v1(76.33,58.17) v1(76.84,58.17)
VDDA_1V8_PHYB: length 0.7
  TOP w0.254: v2(63.79,68.01) U5.K12
  GND_L9 w0.381: 74.04,58.17 v1(74.17,58.17)
  vias: v1(74.68,58.17)
VDDA_1V8_PLL: length 31.6
  TOP w0.254: U11.AE16 v2(65.79,49.61) ; v2(70.99,74.41) U5.B5 ; U11.AD16 v2(65.79,48.81)
  SIG_L10 w0.381: v1(65.53,54.74) 65.53,55.37 62.23,58.67 62.23,65.15 63.12,66.04 66.04,66.04 66.8,66.8 66.8,71.46 66.47,71.79 66.47,72.56 66.99,73.09 69.67,73.09 v2(70.99,74.41)
  BOTTOM w0.381: C29.2 72.38,74.59 71.16,74.59 v2(70.99,74.41)
VIN3A_CLKO: length 54.5
  TOP w0.12: U11.P1 v2(78.59,40.01)
  SIG_L8 w0.094: v2(78.59,40.01) 78.74,40.01 79.27,39.48 82.4,39.48 85.58,42.65 85.58,43.09 91.01,48.51 96.44,48.51 108.3,60.38 111.23,60.38 113.03,62.17 113.03,63.63 115.7,66.29 116.52,66.29 116.71,66.48 v1(116.71,67.05)
  BOTTOM w0.12: P16.50 115.91,66.25 v1(116.71,67.05)
VIN3A_D0: length 59.2
  TOP w0.12: v1(115.82,65.45) 115.74,65.53 R239.1 ; U11.M6 v2(74.59,38.41)
  SIG_L5 w0.094: v2(74.59,38.41) 74.59,38.52 75.01,38.94 75.01,39.36 75.28,39.63 75.59,39.63 75.81,39.85 75.81,40.18 76.14,40.51 76.25,40.51 76.57,40.83 77.06,40.83 77.38,41.15 77.85,41.15 77.98,41.27 78.74,41.27 79.12,41.66 81.53,41.66 82.02,42.14 87.1,42.14 91.06,46.1 95.87,46.1 105.29,55.52 111.23,55.52 115.32,59.61 115.32,64.95 v1(115.82,65.45)
  BOTTOM w0.12: P16.51 v1(115.82,65.45)
VIN3A_D1: length 58.5
  TOP w0.12: R189.1 117.81,66.55 v1(116.71,65.45) ; U11.M2 v2(77.79,38.41)
  SIG_L8 w0.094: v1(116.71,65.45) 116.03,64.77 115.41,64.77 113.82,63.18 113.82,62.02 111.26,59.46 108.68,59.46 96.46,47.24 91.31,47.24 82.3,38.23 80.39,38.23 79.84,38.78 78.16,38.78 v2(77.79,38.41)
  BOTTOM w0.12: v1(116.71,65.45) 115.91,64.65 P16.52
VIN3A_D2: length 67.7
  TOP w0.12: R183.1 118.89,69.6 v1(118.24,70.25) ; U11.L5 v2(75.39,37.61)
  SIG_L8 w0.094: v2(75.39,37.61) 74.96,38.03 74.43,38.03 74.17,38.29 74.17,39.32 74.43,39.58 74.74,39.58 75.01,39.85 75.01,40.16 75.23,40.38 75.54,40.38 76.61,41.45 76.61,41.76 76.83,41.98 77.14,41.98 77.41,42.25 77.41,42.56 77.65,42.8 78.74,42.8 78.99,42.55 78.99,42.42 79.27,42.14 80.62,42.14 81.03,42.55 81.03,43.94 81.92,44.83 82.68,44.83 86.19,48.34 86.19,49.28 93.44,56.54 97.27,56.54 104.62,63.89 107.65,63.89 109.73,65.96 111.04,65.96 115.67,70.6 115.99,70.6 116,70.61 117.87,70.61 v1(118.24,70.25)
  BOTTOM w0.12: P16.16 119.04,69.45 118.24,70.25 v1(118.24,70.25)
VIN3A_D3: length 58.1
  TOP w0.12: v1(118.24,65.45) 118.7,65.91 119.79,65.91 R188.1 ; U11.M1 v2(78.59,38.41)
  SIG_L8 w0.094: v2(78.59,38.41) 79.83,38.41 80.26,37.97 82.42,37.97 90.93,46.48 96.08,46.48 107.28,57.68 111.28,57.68 114.15,60.55 114.15,62.87 115.79,64.52 117.3,64.52 v1(118.24,65.45)
  BOTTOM w0.12: v1(118.24,65.45) 119.04,64.65 P16.22
VIN3A_D4: length 67.9
  TOP w0.12: R182.1 119.49,70.61 v1(119.13,70.25) ; U11.L6 v2(74.59,37.61)
  SIG_L8 w0.094: v2(74.59,37.61) 74.41,37.61 73.99,38.03 73.63,38.03 73.41,38.25 73.41,39.33 73.71,39.63 73.91,39.63 74.21,39.93 74.21,40.13 75.31,41.23 75.51,41.23 75.81,41.53 75.81,41.73 76.11,42.03 76.31,42.03 76.61,42.33 76.61,42.53 76.91,42.83 77.11,42.83 77.41,43.13 77.41,43.33 77.71,43.63 78.88,43.63 79.01,43.5 79.01,43.17 79.22,42.95 80.44,42.95 80.77,43.29 80.77,44.53 81.84,45.59 82.52,45.59 85.97,49.04 85.97,50.25 92.64,56.92 97.08,56.92 104.29,64.14 107.52,64.14 109.65,66.27 111.02,66.27 115.83,71.07 118.71,71.07 119.13,70.65 v1(119.13,70.25)
  BOTTOM w0.12: P16.15 v1(119.13,70.25)
VIN3A_D5: length 64.4
  TOP w0.12: R187.1 119.67,68.07 118.81,68.07 v1(118.24,68.65) ; U11.L4 v2(76.19,37.61)
  SIG_L8 w0.094: v2(76.19,37.61) 76.58,38 76.58,39.37 76.84,39.62 77.14,39.62 77.36,39.85 77.36,40.15 77.72,40.51 77.85,40.51 78.16,40.82 79.01,40.82 79.1,40.92 79.1,40.93 79.34,41.17 80.54,41.17 80.79,40.91 80.79,40.62 81.05,40.36 81.57,40.36 81.98,40.77 82.42,40.77 83.09,41.43 83.09,43.08 93.63,53.63 99.95,53.63 99.95,53.63 100.26,53.63 108.18,61.54 109.02,61.54 112.24,64.77 112.24,65.71 114.22,67.69 117.86,67.69 118.45,68.28 118.45,68.44 v1(118.24,68.65)
  BOTTOM w0.12: v1(118.24,68.65) 119.04,67.85 P16.18
VIN3A_D6: length 54.9
  TOP w0.12: R181.1 115.15,64.52 v1(115.82,63.85) ; U11.L3 v2(76.99,37.61)
  SIG_L8 w0.094: v2(76.99,37.61) 77.38,37.99 79.73,37.99 80.51,37.22 82.05,37.22 91.06,46.23 96.14,46.23 107.24,57.33 111.24,57.33 114.55,60.64 114.55,62.59 v1(115.82,63.85)
  BOTTOM w0.12: P16.53 v1(115.82,63.85)
VIN3A_D7: length 57.3
  TOP w0.12: v1(116.71,63.85) 116.11,63.25 115.57,63.25 115.32,63.5 R180.1 ; U11.L2 v2(77.79,37.61)
  SIG_L8 w0.094: v1(116.71,63.85) 116.71,63.52 116.1,62.91 115.83,62.91 115.32,62.39 115.32,60.78 111.43,56.89 107.66,56.89 95.97,45.2 90.79,45.2 82.3,36.7 79.25,36.7 78.74,37.21 78.18,37.21 v2(77.79,37.61)
  BOTTOM w0.12: P16.54 115.91,63.05 116.71,63.85 v1(116.71,63.85)
VIN3A_D8: length 56.9
  TOP w0.12: R196.1 119.48,63.5 v1(119.13,63.85) ; U11.L1 v2(78.59,37.61)
  SIG_L8 w0.094: v2(78.59,37.61) 78.73,37.61 79.38,36.96 82.17,36.96 91.19,45.98 96.27,45.98 107.4,57.11 111.34,57.11 114.94,60.71 114.94,62.4 116.22,63.68 116.22,64.01 116.47,64.25 119.03,64.25 119.13,64.16 v1(119.13,63.85)
  BOTTOM w0.12: P16.23 v1(119.13,63.85)
VIN3A_D9: length 52.6
  TOP w0.12: v1(115.82,60.65) 115.62,60.45 R195.1 ; U11.K2 v2(77.79,36.81)
  SIG_L8 w0.094: v1(115.82,60.65) 111.12,55.95 107.94,55.95 104.55,52.55 104.55,50.55 102.62,48.62 100.31,48.62 96.67,44.98 90.95,44.98 82.36,36.38 78.21,36.38 v2(77.79,36.81)
  BOTTOM w0.12: P16.57 v1(115.82,60.65)
VIN3A_D10: length 56.5
  TOP w0.12: v1(116.71,62.25) 115.93,61.47 R194.1 ; U11.J1 v2(78.59,36.01)
  SIG_L8 w0.094: v2(78.59,36.01) 82.36,36.01 90.57,44.21 96.28,44.21 100.33,48.26 102.62,48.26 104.87,50.51 104.87,51.79 104.87,51.79 104.87,52.34 108.26,55.73 111.7,55.73 116.71,60.75 v1(116.71,62.25)
  BOTTOM w0.12: P16.56 115.91,61.45 v1(116.71,62.25)
VIN3A_D11: length 57.9
  TOP w0.12: R193.1 115.58,62.48 v1(115.82,62.25) ; U11.J2 v2(77.79,36.01)
  SIG_L8 w0.094: v1(115.82,62.25) 116.23,62.66 116.97,62.66 117.22,62.41 117.22,60.94 111.79,55.51 108.35,55.51 105.09,52.25 105.09,51.88 105.09,50.42 102.61,47.94 100.43,47.94 96.48,43.99 90.73,43.99 82.52,35.78 80.79,35.78 80.16,35.16 79.27,35.16 78.8,35.63 78.16,35.63 v2(77.79,36.01)
  BOTTOM w0.12: P16.55 v1(115.82,62.25)
VIN3A_D12: length 59.6
  TOP w0.12: U11.H1 v2(78.59,35.21) ; R192.1 118.9,64.52 v1(118.24,63.85)
  SIG_L8 w0.094: v1(118.24,63.85) 117.6,63.21 117.6,61.01 111.88,55.29 108.44,55.29 105.31,52.16 105.31,51.97 105.31,50.33 102.61,47.63 100.52,47.63 95.57,42.67 89.79,42.67 82.63,35.51 80.83,35.51 80.25,34.94 79.11,34.94 78.84,35.21 v2(78.59,35.21)
  BOTTOM w0.12: v1(118.24,63.85) 118.24,63.85 119.04,63.05 P16.24
VIN3A_D13: length 64.8
  TOP w0.12: v1(118.24,62.25) 119.02,61.47 R191.1 ; U11.J3 v2(76.99,36.01)
  SIG_L8 w0.094: v2(76.99,36.01) 77.02,36.01 77.36,35.67 77.36,34.27 77.61,34.03 80.04,34.03 80.99,34.97 82.85,34.97 89.53,41.66 97.16,41.66 102.48,46.98 107.03,46.98 112.34,52.3 112.34,54.69 115.46,57.81 117.17,57.81 119.53,60.16 119.53,61.34 119.2,61.68 118.81,61.68 v1(118.24,62.25)
  BOTTOM w0.12: v1(118.24,62.25) 119.04,61.45 P16.26
VIN3A_D14: length 56.6
  TOP w0.12: v1(119.13,60.65) 119.32,60.45 R190.1 ; U11.H2 v2(77.79,35.21)
  SIG_L8 w0.094: v1(119.13,60.65) 117.8,59.33 117.74,59.33 117.37,58.95 117.37,58.94 116.63,58.2 115.37,58.2 112.24,55.07 108.53,55.07 105.53,52.06 105.53,50.23 102.59,47.29 101.4,47.29 96.52,42.42 89.92,42.42 82.76,35.26 80.89,35.26 80.35,34.72 78.95,34.72 78.87,34.8 78.19,34.8 v2(77.79,35.21)
  BOTTOM w0.12: P16.27 v1(119.13,60.65)
VIN3A_D15: length 63.5
  TOP w0.12: U11.H3 v2(76.99,35.21) ; R432.1 119.13,62.32 v1(119.13,62.25) 119.36,62.48 R197.1
  SIG_L8 w0.094: v2(76.99,35.21) 76.99,34.14 77.36,33.76 77.36,33.45 77.58,33.23 78.82,33.23 79.22,33.63 79.95,33.63 81.04,34.72 82.98,34.72 88.56,40.3 96.31,40.3 97.79,41.78 98.55,41.78 103.43,46.66 106.08,46.66 106.18,46.76 107.12,46.76 112.6,52.24 112.6,54.33 115.73,57.46 117.2,57.46 119.79,60.05 119.79,61.59 v1(119.13,62.25)
  BOTTOM w0.12: P16.25 v1(119.13,62.25)
VIN3A_D16: length 70.7
  TOP w0.12: U11.R6 v2(74.59,41.61)
  SIG_L10 w0.094: v1(116.71,78.25) 116.06,77.6 115.39,77.6 110.77,72.97 110.77,70.82 112.01,69.57 112.01,64.69 111.69,64.37 111.69,61.52 110.43,60.26 106.44,60.26 101.17,54.99 89.41,54.99 83.44,49.02 79.77,49.02 79.15,48.41 79.15,48.07 78.73,47.65 78.51,47.65 77.34,46.48 77.34,46.26 77.13,46.05 76.91,46.05 76.54,45.68 76.54,45.46 76.33,45.25 76.11,45.25 75.74,44.88 75.74,44.66 75.53,44.45 75.31,44.45 74.94,44.08 74.94,41.96 v2(74.59,41.61)
  BOTTOM w0.12: P16.36 115.91,77.45 v1(116.71,78.25)
VIN3A_D17: length 63.7
  TOP w0.12: U11.T9 v2(72.19,42.41)
  SIG_L5 w0.094: v1(115.82,71.85) 115.13,71.85 114.05,70.76 114.05,62.76 109.88,58.6 101.27,58.6 94.23,51.56 85.85,51.56 82.17,47.88 81.15,47.88 79.26,45.98 78.37,45.98 78.16,45.78 78.16,45.45 77.94,45.23 77.68,45.23 77.41,44.96 77.41,44.69 77.14,44.43 76.88,44.43 76.61,44.16 76.61,43.89 76.34,43.63 76.08,43.63 75.81,43.36 75.81,43.09 75.54,42.83 75.28,42.83 75.01,42.56 75.01,42.29 74.74,42.03 72.56,42.03 v2(72.19,42.41)
  BOTTOM w0.12: P16.43 v1(115.82,71.85)
VIN3A_D18: length 66.3
  TOP w0.12: U11.T6 v2(74.59,42.41)
  SIG_L5 w0.094: v1(118.24,73.45) 118.24,72.96 117.92,72.64 114.16,72.64 113.54,72.02 113.54,62.87 109.62,58.95 101.11,58.95 93.98,51.82 84.71,51.82 79.72,46.83 78.48,46.83 77.41,45.76 77.41,45.49 77.14,45.23 76.88,45.23 76.61,44.96 76.61,44.69 76.34,44.43 76.05,44.43 75.76,44.14 75.76,43.85 75.54,43.63 75.25,43.63 75.01,43.39 75.01,42.88 74.59,42.46 v2(74.59,42.41)
  BOTTOM w0.12: P16.12 119.04,72.65 v1(118.24,73.45)
VIN3A_D19: length 65.7
  TOP w0.12: U11.T7 v2(73.79,42.41)
  SIG_L5 w0.094: v2(73.79,42.41) 73.79,42.42 74.21,42.84 74.21,43.36 74.48,43.63 74.74,43.63 74.96,43.85 74.96,44.12 75.28,44.43 75.54,44.43 75.81,44.69 75.81,44.96 76.03,45.18 76.34,45.18 76.61,45.45 76.61,45.76 76.83,45.98 77.12,45.98 77.41,46.26 77.41,46.53 78.5,47.62 80.14,47.62 84.58,52.07 93.73,52.07 100.89,59.24 109.38,59.24 113.17,63.03 113.17,72.25 113.79,72.88 116.6,72.88 116.71,72.99 v1(116.71,73.45)
  BOTTOM w0.12: P16.42 115.91,72.65 v1(116.71,73.45)
VIN3A_D20: length 70.9
  TOP w0.12: U11.P6 v2(74.59,40.01)
  SIG_L10 w0.094: v2(74.59,40.01) 74.59,40.3 75.18,40.89 78.75,40.89 79.02,41.17 81.57,41.17 81.94,40.8 84.62,40.8 91.31,47.5 104.98,47.5 115.06,57.58 115.06,71.63 115.7,72.26 116.7,72.26 117.86,73.41 117.86,74.67 v1(118.24,75.05)
  BOTTOM w0.12: v1(118.24,75.05) 119.04,74.25 P16.10
VIN3A_D21: length 69.3
  TOP w0.12: U11.R9 v2(72.19,41.61)
  SIG_L5 w0.094: v1(119.13,71.85) 118.59,72.39 116.44,72.39 116.22,72.17 116.22,71.52 116.08,71.37 115.16,71.37 114.3,70.51 114.3,60.61 111.3,57.61 100.79,57.61 94.49,51.31 85.98,51.31 82.3,47.62 81.41,47.62 78.99,45.21 78.46,45.21 78.16,44.92 78.16,44.65 77.94,44.43 77.68,44.43 77.41,44.16 77.41,43.89 77.14,43.63 76.88,43.63 76.61,43.36 76.61,43.09 76.34,42.83 76.08,42.83 75.81,42.56 75.81,42.29 75.54,42.03 75.28,42.03 75.01,41.76 75.01,41.48 74.68,41.15 72.64,41.15 v2(72.19,41.61)
  BOTTOM w0.12: P16.13 v1(119.13,71.85)
VIN3A_D22: length 70.5
  TOP w0.12: U11.R5 v2(75.39,41.61)
  SIG_L10 w0.094: v2(75.39,41.61) 75.64,41.61 76.02,41.98 76.3,41.98 76.61,42.29 76.61,44.13 76.84,44.36 77.12,44.36 77.43,44.67 77.43,44.95 77.64,45.16 77.84,45.16 78.14,45.46 78.14,45.75 78.44,46.05 79.07,46.05 80.77,47.75 85.34,47.75 91.97,54.38 101.32,54.38 106.76,59.82 110.96,59.82 112.62,61.49 112.62,64.16 112.27,64.52 112.27,71.58 112.7,72.01 112.7,74.35 115.63,77.28 117.27,77.28 v1(118.24,78.25)
  BOTTOM w0.12: P16.6 119.04,77.45 v1(118.24,78.25)
VIN3A_D23: length 61.2
  TOP w0.12: U11.P5 v2(75.39,40.01)
  SIG_L5 w0.094: v2(75.39,40.01) 75.39,40.07 76.08,40.77 76.19,40.77 76.48,41.05 76.96,41.05 77.41,41.49 77.41,41.85 77.59,42.03 80.38,42.03 81.28,42.93 81.53,42.93 81.79,43.18 81.79,43.69 82.04,43.94 88.14,43.94 90.55,46.35 90.55,46.36 91.6,47.41 95.49,47.41 103.91,55.83 111,55.83 115.06,59.89 115.06,69.49 v1(115.82,70.25)
  BOTTOM w0.12: P16.45 v1(115.82,70.25)
VIN3A_DEO: length 69.8
  TOP w0.12: U11.N9 v2(72.19,39.21)
  SIG_L5 w0.094: v1(118.24,71.85) 118.24,71.39 117.58,70.74 115.52,70.74 114.81,70.03 114.81,60.39 111.25,56.83 104.59,56.83 104.42,56.65 102,54.23 101.97,54.23 95.45,47.71 91.52,47.71 88.65,44.83 81.79,44.83 80.9,43.94 80.9,43.31 80.54,42.95 79.34,42.95 79.19,42.8 77.65,42.8 77.36,42.52 77.36,42.25 77.14,42.03 76.88,42.03 76.61,41.76 76.61,41.49 76.26,41.15 76,41.15 75.49,40.64 73.03,40.64 72.56,40.18 72.56,39.58 v2(72.19,39.21)
  BOTTOM w0.12: P16.14 119.04,71.05 v1(118.24,71.85)
VIN3A_FLD: length 67.9
  TOP w0.12: U11.P9 v2(72.19,40.01)
  SIG_L5 w0.094: v1(116.71,71.85) 116.71,71.38 116.33,70.99 115.24,70.99 114.55,70.31 114.55,60.49 111.24,57.18 100.87,57.18 94.74,51.05 86.23,51.05 79.61,44.43 78.48,44.43 78.16,44.12 78.16,43.85 77.94,43.63 77.68,43.63 77.41,43.36 77.41,43.05 77.14,42.78 76.83,42.78 76.61,42.56 76.61,42.25 76.34,41.98 76.03,41.98 75.81,41.76 75.81,41.39 75.31,40.89 72.77,40.89 72.19,40.31 v2(72.19,40.01)
  BOTTOM w0.12: P16.44 115.91,71.05 v1(116.71,71.85)
VIN3A_HSYNC: length 71.5
  TOP w0.12: U11.N7 v2(73.79,39.21)
  SIG_L10 w0.094: v2(73.79,39.21) 74.17,39.59 74.17,40.39 74.93,41.15 78.69,41.15 78.94,41.4 81.66,41.4 82.04,41.02 84.46,41.02 91.19,47.75 98.3,47.75 106.31,55.76 111.11,55.76 114.81,59.46 114.81,71.75 115.57,72.52 116.62,72.52 117.6,73.49 117.6,75.01 118.04,75.45 118.72,75.45 v1(119.13,75.05)
  BOTTOM w0.12: P16.9 v1(119.13,75.05)
VIN3A_VSYNC: length 64.2
  TOP w0.12: U11.R4 v2(76.19,41.61)
  SIG_L10 w0.094: v1(115.82,76.65) 113.03,73.86 113.03,61.54 111.08,59.6 107,59.6 98.45,51.05 90.17,51.05 84.71,45.59 81.28,45.59 80.07,44.38 78.43,44.38 78.21,44.16 78.21,43.85 77.94,43.58 77.63,43.58 77.41,43.36 77.41,42.29 77.1,41.98 76.78,41.98 76.4,41.61 v2(76.19,41.61)
  BOTTOM w0.12: P16.37 v1(115.82,76.65)
VSSA_OSC0: length 5.8
  TOP w0.12: 67.39,52.07 67.39,50.41
  TOP w0.254: 65.66,54.23 67.39,52.5 67.39,52.07 ; 67.39,50.41 U11.AF15
  TOP w0.381: R244.1 61.69,54.32
VSSA_OSC1: length 11.2
  TOP w0.12: U11.AC14 v2(68.19,48.01)
  TOP w0.381: R395.1 68.99,54.32
  GND_L9 w0.094: v2(68.19,48.01) 67.82,48.01 67.31,48.51 67.31,56.39 v1(66.68,57.02)
74801SS: length 2.7
  BOTTOM w0.12: U16.7 104.39,38.6 104.9,39.12 R200.2
AIC_AVDD_DAC3.3: length 6
  TOP w0.254: 56.33,15.31 U18.25
  TOP w0.381: L13.2 54.18,14.86 v1(55.12,14.86) 55.88,14.86 56.33,15.31
  BOTTOM w0.381: C248.1 55.5,15.24 v1(55.12,14.86) C249.1
AIC_BCLK: length 13.5
  TOP w0.12: R231.1 v1(61.72,16.26) 61.45,16.53 U18.2
  INT_L3 w0.094: v1(62.99,26.92) 62.51,26.44 62.51,25.04 62.23,24.77 62.23,16.76 v1(61.72,16.26)
  BOTTOM w0.12: R227.2 v1(62.99,26.92)
AIC_BCLKR: length 2.9
  TOP w0.12: U11.B18 v2(64.19,30.41)
  BOTTOM w0.12: v2(64.19,30.41) 63.79,30.01 63.79,29.34 R227.1
AIC_DIN: length 12.1
  TOP w0.12: R232.1 61.72,17.53 v1(61.72,17.53) U18.4
  INT_L3 w0.094: v1(62.1,26.92) 61.59,26.42 61.59,24.89 61.21,24.51 61.21,18.03 v1(61.72,17.53)
  BOTTOM w0.12: R225.2 v1(62.1,26.92)
AIC_DINR: length 3
  TOP w0.12: U11.B19 v2(63.39,30.41)
  BOTTOM w0.12: R225.1 62.74,29.18 62.74,29.52 63.39,30.17 v2(63.39,30.41)
AIC_DOUT: length 13.4
  TOP w0.12: v1(63.88,26.92) 64.52,26.29 64.52,22.1 64.77,21.84 64.77,18.8 63.97,18 60.93,18 U18.5
  BOTTOM w0.12: R229.2 v1(63.88,26.92)
AIC_DOUTR: length 3.7
  TOP w0.12: U11.C17 v2(64.99,31.21)
  BOTTOM w0.12: R229.1 64.52,29.18 64.52,29.19 64.59,29.25 64.59,30.81 v2(64.99,31.21)
AIC_DRVDD3.3: length 9.7
  TOP w0.254: U18.24 v1(55.12,16.03) ; U18.18 v1(55.12,19.03)
  TOP w0.381: v1(55.12,19.03) 55.05,19.1 L15.2
  SIG_L10 w0.381: v1(55.12,19.03) 55.37,19.03 55.75,18.65 55.75,16.38 55.4,16.03 v1(55.12,16.03)
  BOTTOM w0.381: C259.1 55.25,16.16 v1(55.12,16.03) ; C257.1 54.84,19.3 v1(55.12,19.03) 55.49,19.4 C258.1
AIC_DVDD: length 6.1
  TOP w0.254: v1(60.71,13.72) 60.71,15.05 60.45,15.31 U18.32
  TOP w0.381: C261.1 61.59,13.34 61.21,13.72 v1(60.71,13.72) 59.74,13.72 U19.5
  BOTTOM w0.381: v1(60.71,13.72) 60.71,14.86 60.33,15.24 C262.1
AIC_IOVDD3.3: length 4.1
  TOP w0.254: v1(61.72,19.18) 61.57,19.03 U18.7
  TOP w0.381: L14.2 61.8,19.1 v1(61.72,19.18)
  BOTTOM w0.381: C254.1 62.74,19.18 v1(61.72,19.18) 61.47,19.18 61.25,19.4 C253.1
AIC_MCLK: length 14.6
  TOP w0.12: U18.1 60.89,15.69 61.09,15.49 v1(61.72,15.49)
  INT_L3 w0.094: v1(61.72,15.49) 63.12,16.89 63.12,21.15 64.77,22.8 v1(64.77,26.92)
  BOTTOM w0.12: R223.2 v1(64.77,26.92)
AIC_MCLKR: length 5.1
  TOP w0.12: U11.D18 v2(64.19,32.01)
  BOTTOM w0.12: v2(64.19,32.01) 64.59,31.61 65.15,31.61 65.39,31.37 65.39,30.86 64.9,30.37 64.9,28.67 R223.1
AIC_WCLK: length 18.6
  TOP w0.12: v1(61.72,16.89) 61.58,17.03 U18.3
  BOTTOM w0.12: R224.2 67.39,31.19 66.68,30.48 65.79,30.48 65.19,29.88 65.19,26.71 64.64,26.16 64.64,19.43 62.1,16.89 v1(61.72,16.89)
AIC_WCLKR: length 2
  TOP w0.12: U11.F15 v2(66.59,33.61)
  BOTTOM w0.12: R224.1 67.39,32.81 v2(66.59,33.61)
AM_CAP0: length 1.2
  TOP w0.12: U11.Y15 v2(66.59,45.61)
  BOTTOM w0.254: v2(66.59,45.61) U11.Y15 C141.2
AM_CAP1: length 1.1
  TOP w0.12: U11.J19 v2(63.39,36.01)
  BOTTOM w0.254: v2(63.39,36.01) 63.07,36.32 C143.2
AM_CAP2: length 1.2
  TOP w0.12: U11.P19 v2(63.39,40.01)
  BOTTOM w0.254: C145.2 62.99,40.41 v2(63.39,40.01)
AM_CAP3: length 1.1
  TOP w0.12: U11.Y16 v2(65.79,45.61)
  BOTTOM w0.254: v2(65.79,45.61) 66.1,45.29 C147.2
AM_CAP4: length 1.2
  TOP w0.12: U11.K9 v2(72.19,36.81)
  BOTTOM w0.254: v2(72.19,36.81) 71.79,37.2 C149.2
AM_CAP5: length 1.1
  TOP w0.12: U11.J9 v2(72.19,36.01)
  BOTTOM w0.254: C151.2 71.87,36.32 v2(72.19,36.01)
AM_CAP6: length 1.1
  TOP w0.12: U11.K19 v2(63.39,36.81)
  BOTTOM w0.254: C153.2 63.07,37.12 v2(63.39,36.81)
AM_CAP7: length 1.2
  TOP w0.12: U11.L9 v2(72.19,37.61)
  BOTTOM w0.254: C155.2 71.79,38 v2(72.19,37.61)
AM_CAP8: length 1.1
  TOP w0.12: U11.R20 v2(62.59,41.61)
  BOTTOM w0.254: C142.1 62.9,41.29 v2(62.59,41.61)
AM_CAP9: length 1.1
  TOP w0.12: U11.Y14 v2(68.19,45.61)
  BOTTOM w0.254: v2(68.19,45.61) 67.87,45.29 C144.1
